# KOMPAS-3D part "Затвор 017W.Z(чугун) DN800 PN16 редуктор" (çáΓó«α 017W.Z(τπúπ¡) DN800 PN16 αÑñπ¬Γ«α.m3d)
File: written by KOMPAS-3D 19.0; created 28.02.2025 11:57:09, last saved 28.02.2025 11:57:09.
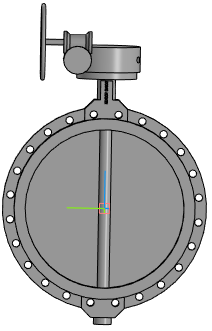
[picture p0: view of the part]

Document properties: Автор: Евгений; Полное имя файла: Затвор 017W.Z(чугун) DN800 PN16 редуктор.a3d

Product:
- Part/product: Затвор 017W.Z(чугун) DN800 PN16 редуктор
    Масса: 541.86

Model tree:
1. Операция без истории:1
